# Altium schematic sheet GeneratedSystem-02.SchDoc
size 168 x 103 mm
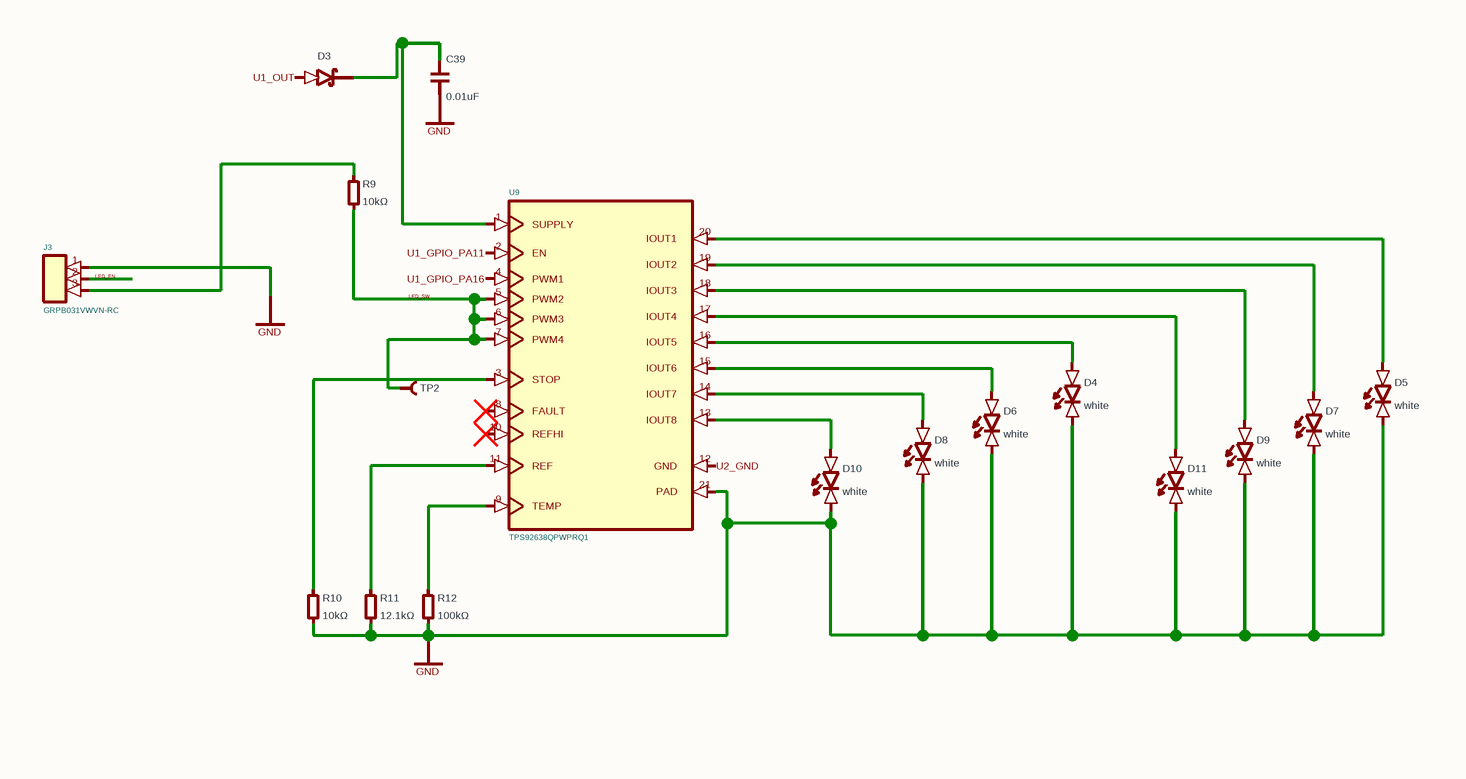
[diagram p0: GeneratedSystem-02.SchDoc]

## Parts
C39  0.01uF
D3  (no value)
D4  white
D5  white
D6  white
D7  white
D8  white
D9  white
D10  white
D11  white
J3  (no value)
R9  10kΩ
R10  10kΩ
R11  12.1kΩ
R12  100kΩ
TP2  (no value)
U9  (no value)

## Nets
GND: C39.2(cathode) D4.2(cathode) D5.2(cathode) D6.2(cathode) D7.2(cathode) D8.2(cathode) D9.2(cathode) D10.2(cathode) D11.2(cathode) J3.1(pin1) R10.2(cathode) R11.2(cathode) R12.2(cathode) U9.21(PAD)
U1_GPIO_PA11: U9.2(EN)
U1_GPIO_PA16: U9.4(PWM1)
U1_OUT: D3.1(pos)
U2_GND: U9.12(GND)
NetC39_1: C39.1(anode) D3.2(neg) U9.1(SUPPLY)
NetD4_1: D4.1(anode) U9.16(IOUT5)
NetD5_1: D5.1(anode) U9.20(IOUT1)
NetD6_1: D6.1(anode) U9.15(IOUT6)
NetD7_1: D7.1(anode) U9.19(IOUT2)
NetD8_1: D8.1(anode) U9.14(IOUT7)
NetD9_1: D9.1(anode) U9.18(IOUT3)
NetD10_1: D10.1(anode) U9.13(IOUT8)
NetD11_1: D11.1(anode) U9.17(IOUT4)
NetJ3_3: J3.3(pin3) R9.1(anode)
NetR9_2: R9.2(cathode) TP2.1(pin1) U9.5(PWM2) U9.6(PWM3) U9.7(PWM4)
NetR10_1: R10.1(anode) U9.3(STOP)
NetR11_1: R11.1(anode) U9.11(REF)
NetR12_1: R12.1(anode) U9.9(TEMP)

Not connected (* = marked no-connect by the designer): J3 2(pin2); U9 8(FAULT)* 10(REFHI)*

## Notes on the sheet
- (near J3) LED_EN
- LED_SW

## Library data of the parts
C39 = capacitor_down
D3 = schottky_diode_right
D4-D11 = led_down
J3 = J3
R9-R12 = boxresistor_down
TP2 = testpoint_right
U9 = U9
